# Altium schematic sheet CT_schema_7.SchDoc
size 274 x 160 mm
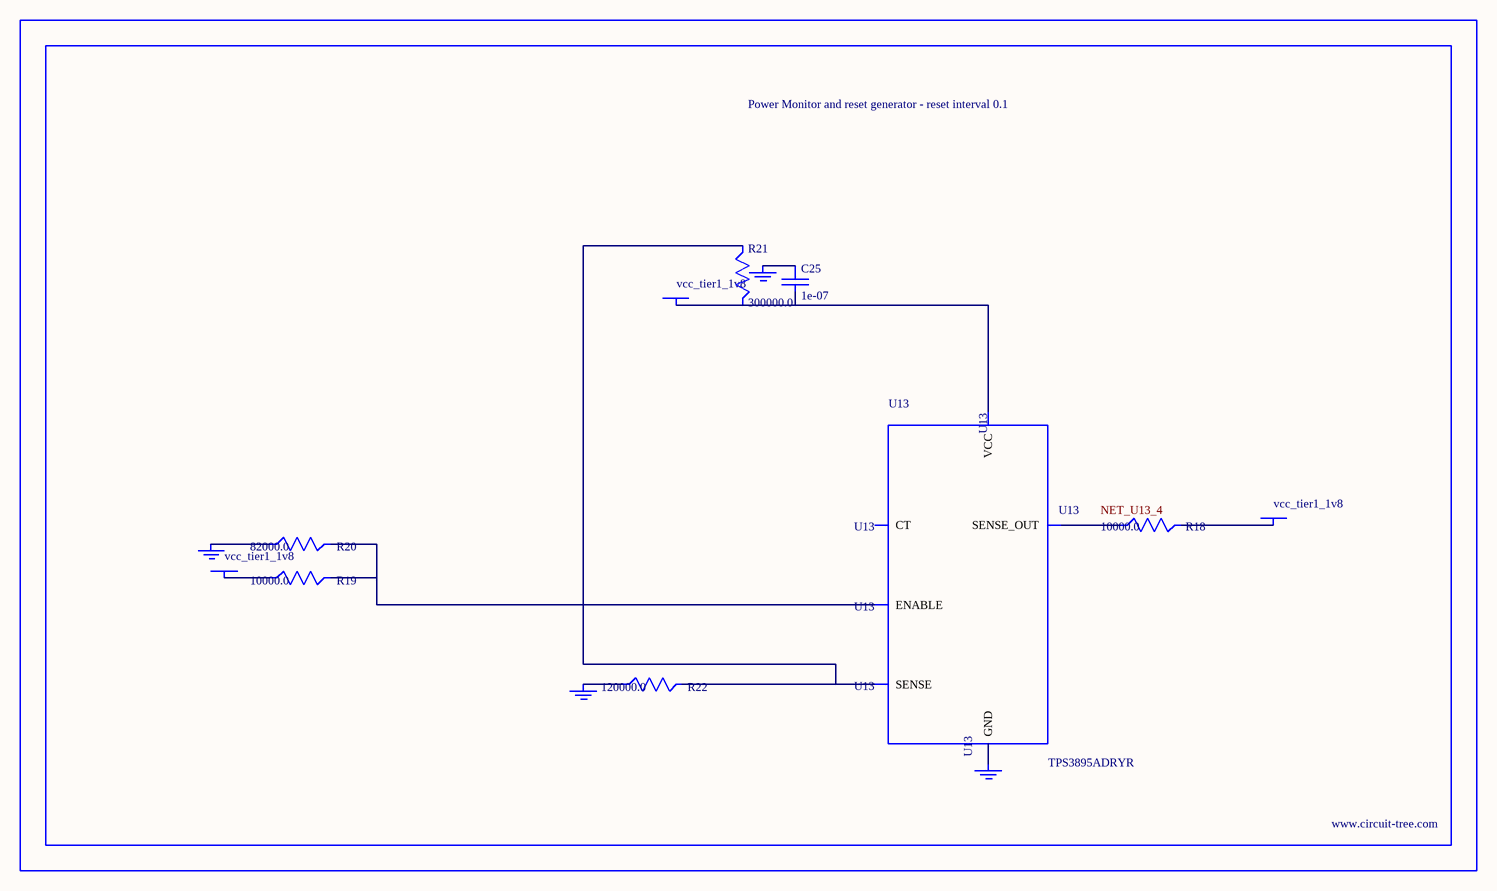
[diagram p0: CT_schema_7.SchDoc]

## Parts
BORDER6  (no value)
C25  1e-07  [C0402]
GND_INSTANCE_6_0  (no value)
GND_INSTANCE_6_1  (no value)
GND_INSTANCE_6_2  (no value)
GND_INSTANCE_6_3  (no value)
POWER_INSTANCE_6_0  vcc_tier1_1v8
POWER_INSTANCE_6_1  vcc_tier1_1v8
POWER_INSTANCE_6_2  vcc_tier1_1v8
R18  10000.0  [R0603]
R19  10000.0  [R0603]
R20  82000.0  [R0603]
R21  300000.0  [R0603]
R22  120000.0  [R0603]
U13  TPS3895ADRYR  [SON-6]

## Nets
NetC25_1: C25.1 GND_INSTANCE_6_2.0(GND)
NetC25_2: C25.2 POWER_INSTANCE_6_2.0(PWR) R21.2 U13.6(VCC)
NetGND_INSTANCE_6_0_0: GND_INSTANCE_6_0.0(GND) R20.1
NetGND_INSTANCE_6_1_0: GND_INSTANCE_6_1.0(GND) R22.1
NetGND_INSTANCE_6_3_0: GND_INSTANCE_6_3.0(GND) U13.2(GND)
NetPOWER_INSTANCE_6_0_0: POWER_INSTANCE_6_0.0(PWR) R19.1
NetPOWER_INSTANCE_6_1_0: POWER_INSTANCE_6_1.0(PWR) R18.2
NetR18_1: R18.1 U13.4(SENSE_OUT)
NetR19_2: R19.2 R20.2 U13.1(ENABLE)
NetR21_1: R21.1 R22.2 U13.3(SENSE)

Not connected (* = marked no-connect by the designer): U13 5(CT)

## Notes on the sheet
- Labels drawn without touching a wire or pin: NET_U13_4

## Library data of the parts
BORDER6 = BORDER_PAGE6
C25 = C0402C104K3RACTU
GND_INSTANCE_6_0-GND_INSTANCE_6_3 = GND
POWER_INSTANCE_6_0-POWER_INSTANCE_6_2 = PWR
R18 R19 = RC0603JR-0710KL
R20 = RC0603JR-0782KL
R21 = RC0603JR-07300KL
R22 = RC0603JR-07120KL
